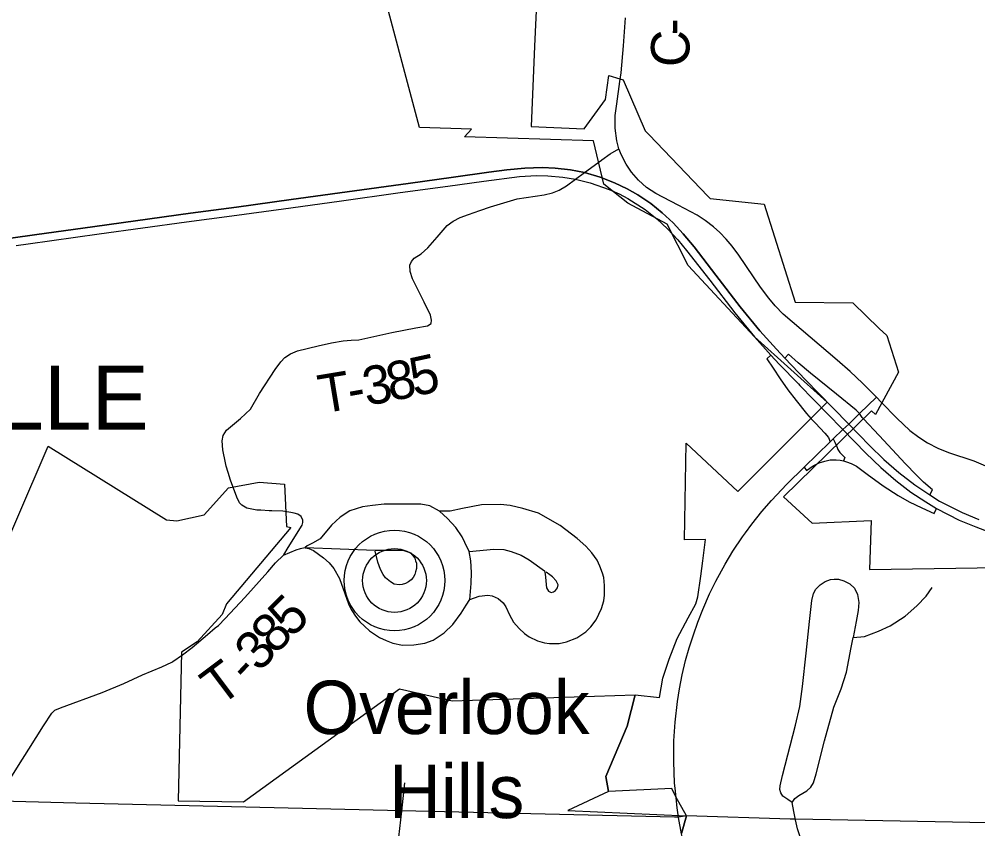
# Model space of a CAD drawing. Extents: x 2402298 to 2498138, y 789485 to 950881.
# Drawn here: x 2469210 to 2476688, y 871312 to 877630 of the extents above; entities that cross this region are included whole.
import ezdxf

# ---------------------------------------------------------------- set-up
doc = ezdxf.new("R2010")
doc.units = 0
for name, color, linetype in [('GM_X_City_Street', 7, 'Continuous'), ('GM_X_Corporation', 7, 'Continuous'), ('GM_X_Corporation_Text', 7, 'Continuous'), ('GM_X_County_Road', 7, 'Continuous'), ('GM_X_County_Road_Text', 7, 'Continuous'), ('GM_X_Interchange_Ramps', 7, 'Continuous'), ('GM_X_Township', 7, 'Continuous'), ('GM_X_Township_Road', 7, 'Continuous'), ('GM_X_Township_Road_Text', 7, 'Continuous'), ('GM_X_Unincorporated', 7, 'Continuous'), ('GM_X_Unincorporated_Text', 7, 'Continuous'), ('GM_X_US_Route', 7, 'Continuous'), ('SC_Scratch1', 7, 'Continuous'), ('SH_Text', 7, 'Continuous')]:
    doc.layers.add(name, color=color, linetype=linetype)

msp = doc.modelspace()

# ---------------------------------------------------------------- linework, layer by layer
at = {"layer": 'GM_X_City_Street'}
for points in [[(2475239.4, 871517.7), (2475205.8, 871541.3), (2475166.7, 871565.5), (2475151.2, 871591.8), (2475143.8, 871618.1), (2475146.5, 871648.4), (2475164.7, 871727.8), (2475265.7, 872119.8), (2475298.7, 872265.3), (2475320.3, 872422.2), (2475348.5, 872682.2), (2475375.5, 872930), (2475393.7, 873093.7), (2475405.1, 873147.5), (2475425.3, 873182.6), (2475458.3, 873216.9), (2475496.7, 873241.8), (2475537.8, 873257.3), (2475567.4, 873260.7), (2475601.1, 873259.3), (2475642.2, 873246.6), (2475688.7, 873224.3), (2475725.7, 873189.3), (2475749.9, 873141.5), (2475760.7, 873078.2), (2475754.3, 873015.2), (2475739.5, 872930), (2475715.9, 872806.1)], [(2475239.4, 871517.7), (2475260.6, 871547.3), (2475291.6, 871572.9), (2475354.3, 871608.6), (2475385.6, 871636.9), (2475405.8, 871671.6), (2475426.7, 871740.3), (2475490.6, 871998.9), (2475563.4, 872262.3), (2475622.6, 872405), (2475663.1, 872535), (2475699.4, 872725.6), (2475715.9, 872806.1), (2475803.1, 872813.2), (2475912.9, 872854.2), (2476003.2, 872896), (2476121.7, 872971.4), (2476211.3, 873050.9), (2476284, 873128.4), (2476330.5, 873193.7)], [(2472110.5, 870127.3), (2472087.3, 870206.1), (2472072.5, 870275.8), (2472081.9, 870393.6), (2472107.8, 870608.2), (2472141.5, 870960.1), (2472171.7, 871247.1), (2472193.6, 871450.2), (2472217.3, 871670.1)], [(2476101.3, 870394.5), (2476061.8, 870479.9), (2476020.7, 870548.6), (2475972.2, 870613.9), (2475904.2, 870677.2), (2475841.5, 870729.7), (2475774.2, 870788.3), (2475634.8, 870909.6), (2475494, 871032.8), (2475358.6, 871153.4), (2475310.8, 871225.4), (2475281.2, 871313), (2475265.6, 871383.3), (2475251.6, 871446.3), (2475239.4, 871517.7)]]:
    msp.add_lwpolyline(points, dxfattribs=at)
at = {"layer": 'GM_X_Corporation'}
for points in [[(2473295.9, 878806), (2473229.5, 877418.4), (2473203.6, 876792), (2473616.7, 876774.3), (2473782.6, 877002.8), (2473809.6, 877191.1), (2473895.4, 877164.1), (2473921.2, 877156), (2474092.1, 876757.5), (2474124, 876727.8), (2474583, 876247.9), (2474599.8, 876230.3), (2475021.1, 876185.9), (2475264.2, 875422.1), (2475711.7, 875415.6), (2475919.4, 875216.6), (2475978, 875160.4), (2476068.4, 874875.6), (2475890.8, 874545.3), (2475858.5, 874573.7), (2475171.4, 873903), (2475394.9, 873697.3), (2475855.6, 873718.7), (2475844.1, 873336.5), (2476850.9, 873350)], [(2474376, 871275.2), (2474415.9, 871412.9), (2474333, 871562.1), (2474300.4, 871627.1), (2473805.9, 871602), (2473784.9, 871720.9), (2473951.4, 872113.2), (2474014.9, 872357.6), (2474203.9, 872337.4), (2474229.9, 872486.9), (2474280.1, 872635.3), (2474341.6, 872798.2), (2474427.4, 872958), (2474489, 873068.8), (2474504.9, 873121.6), (2474526.5, 873282.9), (2474543.8, 873401.9), (2474563.1, 873569.2), (2474399.2, 873566.2), (2474412.8, 874321.8), (2474816.4, 873944.9), (2475512.9, 874640), (2474945.4, 875151.7), (2474428, 875707.3), (2474263.3, 876030.8), (2473958.8, 876193.1), (2473769.7, 876341), (2473688.7, 876681.3), (2472682.5, 876712.7), (2472737.9, 876771), (2472333.8, 876785.1), (2472007.6, 878006.2)], [(2468944.7, 873157.5), (2469436.8, 874298.7), (2470359.7, 873721.9), (2470439.6, 873713.9), (2470652.5, 873760.9), (2470843.5, 873973.6), (2471080.9, 874018.1), (2471280.3, 874001.6), (2471294.9, 873670.7), (2471327.9, 873662.8), (2470825.8, 873068.2), (2470792.6, 872984.3), (2470597.4, 872771.9), (2470475.4, 872689.3), (2470450.5, 871529.1), (2470959.4, 871522), (2472177.2, 872404.8), (2472588.3, 872309.5), (2474014.9, 872357.6), (2473951.4, 872113.2), (2473784.9, 871720.9), (2473805.9, 871602), (2473490.3, 871454.8), (2474415.9, 871412.9), (2474376, 871275.2)]]:
    msp.add_lwpolyline(points, dxfattribs=at)
at = {"layer": 'GM_X_County_Road'}
for p, q in [((2475765.5, 874552.1), (2475896.3, 874679.6)), ((2475896.3, 874679.6), (2475933.5, 874641.4)), ((2474338.7, 871501), (2474328.3, 871607))]:
    msp.add_line(p, q, dxfattribs=at)
for points in [[(2475933.5, 874641.4), (2476056.1, 874515.1), (2476157, 874420.2), (2476226.5, 874367.4), (2476296.3, 874322.7), (2476375.2, 874283.2), (2476460.1, 874249.3), (2476657.4, 874182.7), (2476784.9, 874129.2)], [(2474874.8, 873621.1), (2474924.7, 873689.4), (2475002, 873787), (2475077.2, 873874.3), (2475198.1, 874001.3), (2475334.4, 874133.8), (2475537.3, 874331.4), (2475560.7, 874354), (2475635.4, 874426.9), (2475680.5, 874470.3), (2475765.5, 874552.1)], [(2474328.3, 871607), (2474322.1, 871670.6), (2474315.4, 871834.7), (2474317, 871999.8), (2474326.6, 872144.6), (2474345.2, 872304.9), (2474360.5, 872403.5), (2474382.5, 872514.1), (2474408.8, 872624.5), (2474436.5, 872724.8), (2474468.7, 872824.7), (2474502.7, 872924.3), (2474542.1, 873023.9), (2474596, 873146.5), (2474644.2, 873244.8), (2474716.3, 873377.1), (2474777.2, 873477.5), (2474853, 873591.2), (2474874.8, 873621.1)], [(2474384.3, 871240.4), (2474377, 871272.4), (2474353.1, 871400.8), (2474339.3, 871495.7), (2474338.7, 871501)]]:
    msp.add_lwpolyline(points, dxfattribs=at)
at = {"layer": 'GM_X_Interchange_Ramps'}
for points in [[(2475074.5, 875007), (2475041.5, 874978.2), (2475091, 874906.9), (2475146.6, 874824.1), (2475206.4, 874738.1), (2475269.7, 874653.7), (2475352.3, 874552), (2475388.3, 874512.2)], [(2475765.5, 874552.1), (2475737.6, 874578.2), (2475585.3, 874703), (2475383.5, 874868.5), (2475287.7, 874948.2), (2475210.3, 875016.4), (2475181.3, 874984.5)], [(2475796.9, 874510.1), (2475785.2, 874522.6), (2475765.5, 874552.1)], [(2475388.3, 874512.2), (2475420.8, 874476.4), (2475493.6, 874400.3), (2475522, 874364.7), (2475537.3, 874331.4)], [(2476312.5, 873917.6), (2476333.4, 873956.2), (2476263.3, 874017.1), (2476206.2, 874074.1), (2476123.5, 874161), (2475918.4, 874380.8), (2475796.9, 874510.1)], [(2475560.7, 874354), (2475571.6, 874329.6), (2475584.3, 874299.2)], [(2475584.3, 874299.2), (2475589.4, 874287), (2475596.9, 874272.2), (2475612.1, 874248.3), (2475631.1, 874227.3), (2475650.1, 874209.8), (2475638.9, 874183.8)], [(2475334.4, 874133.8), (2475352.7, 874109), (2475404.1, 874144.7), (2475439.8, 874161.7)], [(2475439.8, 874161.7), (2475450, 874166.6), (2475493.9, 874181.9), (2475535.5, 874189.9), (2475581.8, 874191.8), (2475615.3, 874188.6), (2475638.9, 874183.8), (2475664.7, 874176.3), (2475699.8, 874163.7), (2475741.1, 874140.9), (2475824.1, 874079.5), (2475948.8, 873988.9), (2476067, 873912.9), (2476152.9, 873864.5), (2476250.5, 873815.7), (2476348.5, 873772.4), (2476366.8, 873811.3)]]:
    msp.add_lwpolyline(points, dxfattribs=at)
at = {"layer": 'GM_X_Township'}
msp.add_lwpolyline([(2478122.4, 871331.4), (2475264.5, 871386.2), (2475224.5, 871387), (2474415.9, 871412.9), (2474352.1, 871403.7), (2474322.4, 871404.2), (2472192.6, 871453.1), (2469651.1, 871511.4), (2468967.7, 871531.4), (2468934.1, 871536.6), (2468798, 871539.9), (2467941.6, 871563.7), (2467399.3, 871578.7), (2467075, 871587.8), (2466785.7, 871595.8), (2464988.8, 871612.2), (2461420.7, 871696.8), (2460458.8, 871708.7), (2460429.8, 871709.1), (2460401.3, 871709.4), (2459688.5, 871718)], dxfattribs=at)
at = {"layer": 'GM_X_Township_Road'}
for points in [[(2473756, 876532.4), (2473819.3, 876577.5), (2473887.2, 876617.8)], [(2472802.7, 876135.8), (2472887, 876165.4), (2473095.5, 876226.9), (2473304.1, 876259.7), (2473369.8, 876273.7), (2473421.3, 876294.4), (2473478.4, 876329.1), (2473548.3, 876381.2), (2473619.2, 876432.8), (2473751.8, 876529.4), (2473756, 876532.4)], [(2470840.1, 874092.2), (2470824.1, 874142.8), (2470819.1, 874168), (2470799, 874268.5), (2470792.5, 874340.6), (2470800.9, 874381.6), (2470825.9, 874421.4), (2470937, 874512.9), (2471013.3, 874585.9), (2471085.4, 874708.9), (2471206.8, 874894.8), (2471249.8, 874956), (2471283, 874988.4), (2471325.3, 875018.3), (2471381.7, 875040.7), (2471543.3, 875081.4), (2471646.8, 875105), (2471736, 875119), (2471799.9, 875124.5), (2471860.5, 875127.8), (2472116.1, 875183.4), (2472303.7, 875220.7), (2472395.7, 875236.5), (2472422.3, 875255.6), (2472427.3, 875281.3), (2472417.3, 875321.1), (2472368.3, 875420.7), (2472318.6, 875520.3), (2472276.9, 875602.3), (2472260.2, 875659.9), (2472258.3, 875710), (2472270.8, 875739.2), (2472291.2, 875763.4), (2472344.4, 875797.6), (2472397.1, 875845), (2472471.3, 875929.4), (2472517.4, 875983.9), (2472549.3, 876020.3), (2472595.9, 876053.7), (2472648.8, 876081.3), (2472713.6, 876104.5), (2472802.7, 876135.8)], [(2471181.2, 873793.6), (2471159.9, 873794.3), (2471095.5, 873797.1), (2471063.4, 873798.5), (2470986.4, 873815.2), (2470945.4, 873836.1), (2470928.3, 873855), (2470907.1, 873898.9), (2470859.3, 874031.4), (2470840.1, 874092.2)], [(2471272.4, 873446.5), (2471371.6, 873489.8), (2471404.6, 873500.4), (2471437.8, 873505.9), (2471439.6, 873505.4), (2471470, 873498.5), (2471504.9, 873484.8), (2471582.7, 873427.3), (2471627.7, 873386.4), (2471663.7, 873344.2), (2471709.7, 873264), (2471778.1, 873068), (2471800.4, 873023), (2471832.7, 872971.5), (2471868.2, 872927.8), (2471902.4, 872893.6), (2471941.4, 872856.6), (2472020.4, 872805.3), (2472071.4, 872781.9), (2472124.7, 872759.5), (2472199.7, 872745.7), (2472287.9, 872747.7), (2472373.3, 872761.5), (2472439.1, 872785.2), (2472524.6, 872840.4), (2472593.6, 872905.5), (2472658.1, 872994.9), (2472696.3, 873056.1), (2472724.5, 873100.8), (2472798.2, 873127.2), (2472864.6, 873135), (2472898.8, 873130.4), (2472945.5, 873109.4), (2472985, 873076.5), (2473004.7, 873044.3), (2473035.6, 872981.8), (2473065.9, 872925.3), (2473109.9, 872874.6), (2473151.7, 872837.1), (2473189.2, 872810.8), (2473254, 872779.6), (2473307.6, 872762.8), (2473346.1, 872757.5), (2473422.3, 872756.9), (2473479.6, 872770.7), (2473559.8, 872801.6), (2473630.2, 872848.9), (2473669.7, 872888.4), (2473711.1, 872942.3), (2473751.2, 873031.8), (2473770.9, 873091), (2473776.8, 873135), (2473776.8, 873210.7), (2473770.3, 873273.2), (2473759.8, 873306.7), (2473740, 873361.3), (2473718.3, 873407.3), (2473677.5, 873465.9), (2473628.9, 873516.5), (2473563.1, 873577), (2473428.6, 873679.8), (2473261.7, 873774.2), (2473139.1, 873810.7), (2473039, 873834.2), (2472965.3, 873843.4), (2472817.3, 873839.4), (2472667.6, 873811), (2472571.3, 873790.8), (2472488.8, 873790.2), (2472412.1, 873832.2), (2472343.7, 873845.4), (2472055.7, 873844.1), (2471965.5, 873835.7), (2471887.3, 873823.9), (2471790.2, 873792.4), (2471713.2, 873742.7), (2471646.6, 873682.2), (2471557.1, 873575.7), (2471498.5, 873540.2), (2471456.6, 873520.6), (2471440.1, 873507.4)], [(2471275.1, 873451.1), (2471306.9, 873506), (2471418.1, 873681.9), (2471422.2, 873702.4), (2471421.6, 873720.4), (2471408.5, 873748), (2471383.5, 873767.7), (2471355.7, 873775.9), (2471327.6, 873781.1), (2471266.3, 873790.9), (2471181.2, 873793.6)], [(2472724.5, 873100.8), (2472735.7, 873225.2), (2472737.7, 873312.6), (2472731.8, 873402.7), (2472719.9, 873476.4), (2472687, 873545.5), (2472665.4, 873591.5), (2472616, 873662.5), (2472550.9, 873733.6), (2472488.8, 873790.2)], [(2471440.1, 873507.4), (2471987.1, 873486), (2472059.7, 873486.4), (2472201.6, 873487.3), (2472234.4, 873476.9), (2472262.1, 873465.3), (2472278.7, 873447.4), (2472294.9, 873423), (2472302.4, 873402.6), (2472308.2, 873384.8), (2472308.6, 873363.6), (2472308.2, 873343.3), (2472302, 873318), (2472296.2, 873297.7), (2472284.1, 873272.8), (2472268.4, 873254.5), (2472247.2, 873237.9), (2472224, 873225.5), (2472196.2, 873218.8), (2472173.8, 873216.8), (2472133.9, 873221.3), (2472105.7, 873237.9), (2472068.4, 873269.1), (2472050.1, 873297.7), (2472028.6, 873335.9), (2472007.8, 873391.9), (2471987.5, 873478.1)], [(2472719.9, 873476.4), (2472912, 873494.8), (2472991.6, 873490.9), (2473047.5, 873477.1), (2473125.1, 873447.5), (2473187.6, 873411.3), (2473307.3, 873324.5), (2473311.9, 873298.2), (2473319.1, 873249.5), (2473321.1, 873216.6), (2473324.4, 873191.6), (2473338.8, 873166.6), (2473359.2, 873155.4), (2473378.3, 873161.3), (2473394.1, 873171.2), (2473409.8, 873191.6), (2473413.8, 873216.6), (2473399.4, 873246.2), (2473370.4, 873278.4), (2473349.4, 873294.9), (2473321.1, 873315.9)], [(2470739.4, 872879), (2470763.3, 872899.5), (2470816.4, 872954.1), (2470970.5, 873117.2), (2471149.9, 873317.1), (2471208.7, 873388.4), (2471272.4, 873446.5), (2471275.1, 873451.1)], [(2470407.7, 872617.4), (2470484.5, 872670.4), (2470560, 872728), (2470679.5, 872827.8), (2470739.4, 872879)], [(2468853, 871420.2), (2468888.5, 871450), (2468913.6, 871485.7), (2468936.5, 871507.7), (2468961.8, 871524.4), (2468968.7, 871528.5), (2469031.7, 871566.1), (2469069.2, 871601.4), (2469117.4, 871668.9), (2469203.5, 871806.2), (2469284.3, 871933.7), (2469400.4, 872116.5), (2469463.7, 872214.8), (2469488.8, 872236.8), (2469530.8, 872254.9), (2469856.3, 872374.5), (2470026.7, 872445), (2470171.2, 872512.6), (2470323.7, 872575.9), (2470399.2, 872611.6), (2470407.7, 872617.4)]]:
    msp.add_lwpolyline(points, dxfattribs=at)
at = {"layer": 'GM_X_Unincorporated'}
for radius in [392.8, 249]:
    msp.add_circle((2472137.5, 873249.5), radius, dxfattribs=at)
at = {"layer": 'GM_X_US_Route'}
for points in [[(2469011.9, 875903), (2469328.7, 875946.6), (2469799, 876012.3), (2470116.8, 876055.8), (2470546.8, 876116.1), (2470906.2, 876163.5), (2471330.4, 876222.1), (2471768.3, 876282.6), (2472243.1, 876348.6), (2472598.4, 876397.7), (2472873.9, 876435.8), (2473013.3, 876455), (2473154.6, 876468.1), (2473290.7, 876472.3), (2473390.1, 876467.5), (2473509.2, 876452.8), (2473619.2, 876432.8), (2473741.2, 876396.1), (2473854.6, 876351.8), (2473952.6, 876305.7), (2474034.6, 876257.7), (2474136, 876190.6), (2474226, 876118.8), (2474310.2, 876041), (2474389, 875955.3), (2474474.8, 875853.3), (2474644, 875633.3), (2474835, 875384.9), (2474988.3, 875198.3), (2475116.7, 875053.4), (2475181.3, 874984.5), (2475344.4, 874815.5), (2475557.2, 874596.2), (2475680.5, 874470.3), (2475843, 874304), (2475955.8, 874193.2), (2476072, 874091.3), (2476196.1, 873994.8), (2476312.5, 873917.6), (2476390.2, 873869.8), (2476566.4, 873779.4), (2476694.5, 873725.8)], [(2469185.4, 875863), (2469280, 875876.1), (2469833.7, 875954.4), (2470514.5, 876048.2), (2470868.3, 876094.3), (2471271.4, 876150.6), (2471706.2, 876210.1), (2472182.7, 876276), (2472552.6, 876327.5), (2472834.6, 876365.5), (2473113.3, 876400.9), (2473244.1, 876409), (2473334.7, 876407.3), (2473449.9, 876397.7), (2473548.3, 876381.2), (2473662.8, 876353.7), (2473811.2, 876301.7), (2473891.1, 876265.8), (2473956.5, 876229.9), (2474093.8, 876144.1), (2474183.8, 876072.3), (2474268, 875994.6), (2474346.8, 875908.8), (2474416.5, 875824.1), (2474596.6, 875592), (2474792.8, 875338.4), (2474946.1, 875151.9), (2475074.5, 875007)], [(2475074.5, 875007), (2475139.1, 874938), (2475288.7, 874783.2)], [(2475288.7, 874783.2), (2475299.3, 874772.1), (2475512.2, 874552.9), (2475635.4, 874426.9), (2475814.5, 874243.6), (2475931.9, 874130.4), (2476047.7, 874029.7), (2476166.1, 873939.6), (2476282.5, 873862.4), (2476366.8, 873811.3), (2476543, 873720.9), (2476671.1, 873667.3), (2476786.9, 873624.4), (2476915.6, 873586.9), (2477057.6, 873553.6), (2477196.4, 873529.5), (2477329.4, 873516.7), (2477360.8, 873514.9)]]:
    msp.add_lwpolyline(points, dxfattribs=at)
at = {"layer": 'SC_Scratch1'}
for p, q in [((2473923.3, 877421.6), (2473940.4, 877640.3)), ((2473904.5, 877212), (2473923.3, 877421.6)), ((2473895.4, 877143.5), (2473904.5, 877212)), ((2473872.4, 876969.7), (2473895.4, 877143.5)), ((2473860, 876879.1), (2473872.4, 876969.7)), ((2473858.4, 876777.8), (2473860, 876879.1)), ((2473872.9, 876679.7), (2473858.4, 876777.8)), ((2473887.2, 876617.7), (2473872.9, 876679.7)), ((2473908.8, 876568.4), (2473887.2, 876617.7)), ((2473944.8, 876497.9), (2473908.8, 876568.4)), ((2473987.3, 876434.5), (2473944.8, 876497.9)), ((2474040.1, 876374.6), (2473987.3, 876434.5)), ((2474103.8, 876317.3), (2474040.1, 876374.6)), ((2474175.1, 876269.1), (2474103.8, 876317.3)), ((2474349.2, 876178.5), (2474175.1, 876269.1)), ((2474499.8, 876099.2), (2474349.2, 876178.5)), ((2474560.9, 876058.6), (2474499.8, 876099.2)), ((2474626.1, 876009.3), (2474560.9, 876058.6)), ((2474676.6, 875965.7), (2474626.1, 876009.3)), ((2474725.9, 875914.1), (2474676.6, 875965.7)), ((2474772.6, 875858.7), (2474725.9, 875914.1)), ((2474824.5, 875787.8), (2474772.6, 875858.7)), ((2474937.6, 875620.1), (2474824.5, 875787.8)), ((2474992.2, 875539.7), (2474937.6, 875620.1)), ((2475057.8, 875452), (2474992.2, 875539.7)), ((2475108.3, 875391.7), (2475057.8, 875452)), ((2475169.3, 875328.8), (2475108.3, 875391.7)), ((2475309.3, 875207.8), (2475169.3, 875328.8)), ((2475589.7, 874969.5), (2475309.3, 875207.8)), ((2475692.1, 874880.8), (2475589.7, 874969.5)), ((2475789.2, 874789.3), (2475692.1, 874880.8)), ((2475896.4, 874679.6), (2475789.2, 874789.3))]:
    msp.add_line(p, q, dxfattribs=at)
at = {"layer": 'SH_Text'}
for p, q in [((2473923.3, 877421.6), (2473940.4, 877640.3)), ((2473904.5, 877212), (2473923.3, 877421.6)), ((2473895.4, 877143.5), (2473904.5, 877212)), ((2473872.4, 876969.7), (2473895.4, 877143.5)), ((2473860, 876879.1), (2473872.4, 876969.7)), ((2473858.4, 876777.8), (2473860, 876879.1)), ((2473872.9, 876679.7), (2473858.4, 876777.8)), ((2473887.2, 876617.8), (2473872.9, 876679.7)), ((2473908.8, 876568.4), (2473887.2, 876617.8)), ((2473944.8, 876497.9), (2473908.8, 876568.4)), ((2473987.3, 876434.5), (2473944.8, 876497.9)), ((2474040.1, 876374.6), (2473987.3, 876434.5)), ((2474103.8, 876317.3), (2474040.1, 876374.6)), ((2474175.1, 876269.1), (2474103.8, 876317.3)), ((2474349.2, 876178.5), (2474175.1, 876269.1)), ((2474499.8, 876099.2), (2474349.2, 876178.5)), ((2474560.9, 876058.6), (2474499.8, 876099.2)), ((2474626.1, 876009.3), (2474560.9, 876058.6)), ((2474676.6, 875965.7), (2474626.1, 876009.3)), ((2474725.9, 875914.1), (2474676.6, 875965.7)), ((2474772.6, 875858.7), (2474725.9, 875914.1)), ((2474824.5, 875787.8), (2474772.6, 875858.7)), ((2474937.6, 875620.1), (2474824.5, 875787.8)), ((2474992.2, 875539.7), (2474937.6, 875620.1)), ((2475057.8, 875452), (2474992.2, 875539.7)), ((2475108.3, 875391.7), (2475057.8, 875452)), ((2475169.3, 875328.8), (2475108.3, 875391.7)), ((2475309.3, 875207.8), (2475169.3, 875328.8)), ((2475589.7, 874969.5), (2475309.3, 875207.8)), ((2475692.1, 874880.8), (2475589.7, 874969.5)), ((2475789.2, 874789.3), (2475692.1, 874880.8)), ((2475896.3, 874679.6), (2475789.2, 874789.3)), ((2475765.5, 874552.1), (2475896.3, 874679.6))]:
    msp.add_line(p, q, dxfattribs=at)
for points in [[(2475181.3, 874984.5), (2475116.7, 875053.4), (2474988.3, 875198.3), (2474835, 875384.9), (2474644, 875633.3), (2474474.8, 875853.3), (2474389, 875955.3), (2474310.2, 876041), (2474226, 876118.8), (2474136, 876190.6), (2474034.6, 876257.7), (2473952.6, 876305.7), (2473854.6, 876351.8), (2473741.2, 876396.1), (2473619.2, 876432.8), (2473509.2, 876452.8), (2473390.1, 876467.5), (2473290.7, 876472.3), (2473154.6, 876468.1), (2473013.3, 876455), (2472873.9, 876435.8), (2472598.4, 876397.7), (2472243.1, 876348.6), (2471768.3, 876282.6), (2471330.4, 876222.1), (2470906.2, 876163.5), (2470546.8, 876116.1), (2470116.8, 876055.8), (2469799, 876012.3), (2469328.7, 875946.6), (2469011.9, 875903)], [(2469185.4, 875863), (2469280, 875876.1), (2469833.7, 875954.4), (2470514.5, 876048.2), (2470868.3, 876094.3), (2471271.4, 876150.6), (2471706.2, 876210.1), (2472182.7, 876276), (2472552.6, 876327.5), (2472834.6, 876365.5), (2473113.3, 876400.9), (2473244.1, 876409), (2473334.7, 876407.3), (2473449.9, 876397.7), (2473548.3, 876381.2), (2473662.8, 876353.7), (2473811.2, 876301.7), (2473891.1, 876265.8), (2473956.5, 876229.9), (2474093.8, 876144.1), (2474183.8, 876072.3), (2474268, 875994.6), (2474346.8, 875908.8), (2474416.5, 875824.1), (2474596.6, 875592), (2474792.8, 875338.4), (2474946.1, 875151.9), (2475074.5, 875007)], [(2475074.5, 875007), (2475041.5, 874978.2), (2475091, 874906.9), (2475146.6, 874824.1), (2475206.4, 874738.1), (2475269.7, 874653.7), (2475352.3, 874552), (2475388.3, 874512.2)], [(2475765.5, 874552.1), (2475737.6, 874578.2), (2475585.3, 874703), (2475383.5, 874868.5), (2475287.7, 874948.2), (2475210.3, 875016.4), (2475181.3, 874984.5)], [(2475537.3, 874331.4), (2475560.7, 874354), (2475635.4, 874426.9), (2475680.5, 874470.3), (2475765.5, 874552.1)], [(2475388.3, 874512.2), (2475420.8, 874476.4), (2475493.6, 874400.3), (2475522, 874364.7), (2475537.3, 874331.4)]]:
    msp.add_lwpolyline(points, dxfattribs=at)

# ---------------------------------------------------------------- texts
at = {"layer": 'GM_X_Corporation_Text'}
msp.add_text('WINTERSVILLE', height=500, rotation=0.00001, dxfattribs=at).set_placement((2465315.9, 874426.9))
at = {"layer": 'GM_X_County_Road_Text'}
for s, rotation, p in [('-', 88.92863, (2474440.9, 877500.8)), ('C', 88.62213, (2474434.9, 877252.8))]:
    msp.add_text(s, height=300, rotation=rotation, dxfattribs=at).set_placement(p)
at = {"layer": 'GM_X_Township_Road_Text'}
for s, rotation, p in [('8', 11.52637, (2472105.9, 874646.4)), ('5', 12.22967, (2472290.9, 874684.1)), ('3', 10.71143, (2471919.7, 874611.2)), ('T', 9.42357, (2471569.8, 874551.8)), ('-', 9.97925, (2471794.3, 874589.1)), ('5', 44.49954, (2471332.7, 872795.1)), ('8', 46.58991, (2471207.8, 872663)), ('3', 47.71259, (2471084.5, 872527.4)), ('T', 36.90332, (2470775.4, 872261.1)), ('-', 46.99247, (2470997.6, 872434.3))]:
    msp.add_text(s, height=300, rotation=rotation, dxfattribs=at).set_placement(p)
at = {"layer": 'GM_X_Unincorporated_Text'}
for s, p in [('Overlook', (2471427.9, 872051.3)), ('Hills', (2472096.7, 871395.7))]:
    msp.add_text(s, height=417, rotation=0.00001, dxfattribs=at).set_placement(p)

doc.saveas('drawing.dxf')
